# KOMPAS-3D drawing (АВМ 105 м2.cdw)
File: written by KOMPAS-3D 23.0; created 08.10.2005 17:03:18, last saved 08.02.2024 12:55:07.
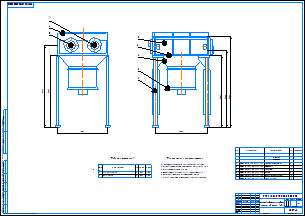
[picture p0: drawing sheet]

Sheet 1: A1, landscape

Document properties: Полное имя файла: G:\Учёба\Курсовое проектирование\ПиА курсовой проект\АВО Артур Абдуллин\Для публикации\АВМ 105 м2.cdw

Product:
- Part/product: (unnamed)  | designation УТЭК.18.02.09.ПП.00.00.000.ВО

Title block, sheet 1: Наименование: Аппарат воздушного охлаждения / Чертеж общего вида; designation: УТЭК.18.02.09.ПП.00.00.000.ВО; scale: 1:20; Количество листов документа: 1; organisation: 3ПНГ-3; Форматы листов документа: A1; stored path: C:\Documents and Settings\Администратор\Мои документы\Курсовой проект\Чертеж.cdw

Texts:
  Normal
  Техническая характеристика
  Аппарат предназначен для охлаждения керосина
  Производительность аппарата по сырью 41,67 кг/с
  Поверхность секции 105 м2
  Температура среды на входе в аппарат 200␣С
  Symbol
  Давление в трубном пространстве 1 МПа
  Среда в аппарате нетоксичная, слабокоррозионная
  Таблица штуцеров
  Обоз-
  наче-
  ние
  Кол.
  Dу, мм
  Pу, МПа
  Ввод паров смеси
  Вывод смеси
  Поз.
  УТЭК 18.02.09 ПП.00.00.001
  Металоконструкция
  Детали
  УТЭК 18.02.09 ПП.00.00.002
  Диффузор
  УТЭК 18.02.09 ПП.00.00.003
  Коллектор
  УТЭК 18.02.09 ПП.00.00.004
  Жалюзи
  УТЭК 18.02.09 ПП.00.00.005
  Теплообменная секция
  УТЭК 18.02.09 ПП.00.00.006
  Рамка сборная
Dimensions and other numbers on the sheet: 2; 1; 250; 0,25; 4; 3; 5; 6; 1425; 1250; 1435; 1810; 1380; 1700; 1:20; 3ПНГ-3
